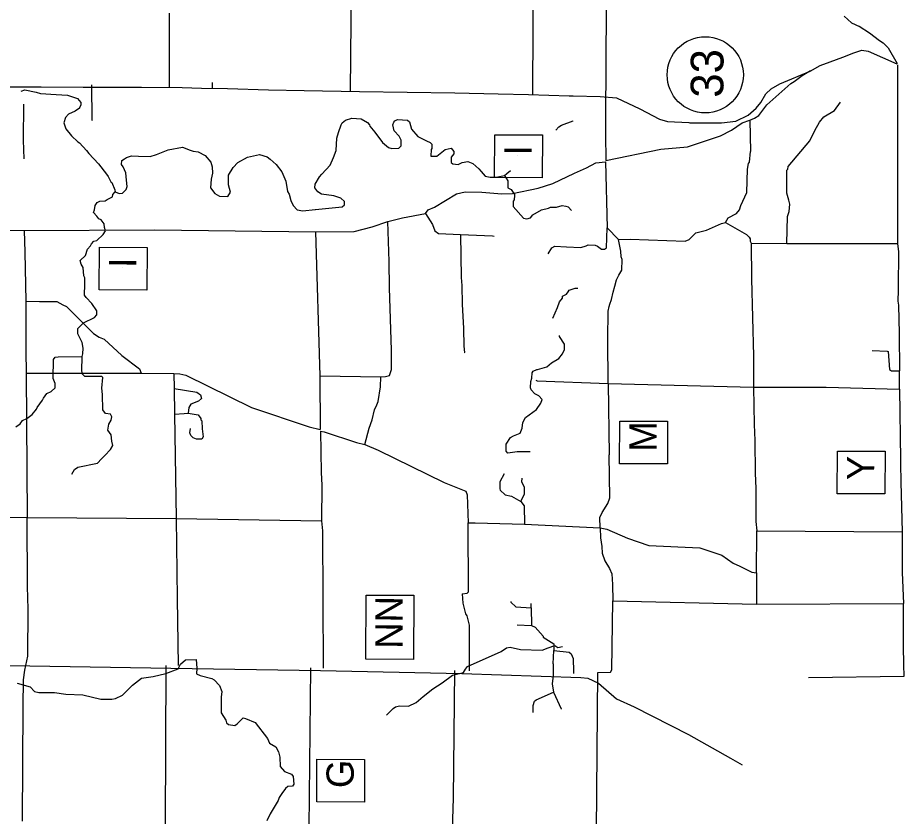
# Model space of a CAD drawing. Extents: x 299354 to 1325680, y 96128 to 228242.
# Drawn here: x 367783 to 400316, y 158651 to 187967 of the extents above; entities that cross this region are included whole.
import ezdxf

# ---------------------------------------------------------------- set-up
doc = ezdxf.new("R2010")
doc.units = 0
for name, color, linetype in [('Level 12', 7, 'Continuous'), ('Level 13', 7, 'Continuous'), ('Level 2', 7, 'Continuous'), ('Level 3', 7, 'Continuous'), ('Level 4', 7, 'Continuous'), ('Level 57', 7, 'Continuous')]:
    doc.layers.add(name, color=color, linetype=linetype)

msp = doc.modelspace()

# ---------------------------------------------------------------- linework, layer by layer
at = {"layer": 'Level 12'}
msp.add_line((393013, 185872), (393013, 185872), dxfattribs=at)
msp.add_circle((393013, 185872), 1398, dxfattribs=at)
at = {"layer": 'Level 13'}
for p, q in [((386137, 182916), (386137, 182916)), ((371631, 178789), (371631, 178789)), ((390728, 172406), (390728, 172406)), ((398712, 171305), (398712, 171305)), ((381418, 165641), (381418, 165641)), ((379612, 159993), (379612, 159993))]:
    msp.add_line(p, q, dxfattribs=at)
for points in [[(387031, 182095), (385281, 182102), (385287, 183672), (387037, 183665)], [(372525, 177967), (370775, 177974), (370782, 179544), (372532, 179537)], [(391622, 171585), (389872, 171592), (389879, 173162), (391629, 173155)], [(399606, 170484), (397856, 170491), (397862, 172061), (399612, 172054)], [(382311, 164410), (380561, 164417), (380570, 166772), (382320, 166765)], [(380506, 159171), (378756, 159178), (378762, 160748), (380512, 160741)]]:
    msp.add_lwpolyline(points, close=True, dxfattribs=at)
at = {"layer": 'Level 2'}
for points in [[(389386, 190375), (389347, 184284)], [(398113, 188030), (398378, 187777)], [(398378, 187777), (398678, 187650)], [(398656, 187660), (399042, 187413)], [(399042, 187413), (399406, 187135)], [(399406, 187135), (399547, 187050), (399729, 186865)], [(396860, 186008), (397233, 186212), (397597, 186345), (398063, 186521), (398461, 186680), (398765, 186780), (398992, 186743), (400048, 186276)], [(399729, 186865), (400055, 186283)], [(400065, 186237), (400065, 185837)], [(366798, 185430), (368641, 185430), (370184, 185424), (372319, 185421), (373812, 185408), (374529, 185385), (375479, 185368), (376980, 185321), (378289, 185292), (380324, 185257), (383818, 185209), (385410, 185178), (386528, 185151), (388020, 185104), (388170, 185103), (389154, 185077), (389762, 185022), (390609, 184623), (391331, 184249), (391622, 184155), (392414, 184115), (392448, 184114), (393615, 184104), (394141, 184174), (394585, 184387), (394879, 184651), (395048, 184857), (395235, 185172), (395428, 185362), (395747, 185543), (396860, 186008)], [(400065, 185837), (400067, 181020)], [(389347, 184284), (389358, 183675)], [(389358, 183675), (389366, 182725)], [(382844, 180918), (383078, 181016), (383883, 181500), (384201, 181580), (384818, 181558), (385543, 181502), (385935, 181515), (386879, 181715), (387423, 181876), (388211, 182261), (388654, 182457), (388998, 182637), (389349, 182676)], [(389349, 182676), (389410, 180250)], [(382743, 180785), (382844, 180918)], [(400067, 181020), (400071, 179678)], [(381364, 180489), (381907, 180618), (382743, 180785)], [(378716, 180105), (380126, 180117), (380787, 180295), (381364, 180489)], [(389410, 180250), (389831, 179821)], [(368013, 180152), (372813, 180184), (378716, 180105)], [(389449, 174541), (389439, 176166), (389448, 177200), (389491, 177366), (389509, 177457), (389577, 177623), (389630, 177890), (389698, 178114), (389751, 178347), (389836, 178521), (389954, 178703), (389958, 179095), (389925, 179195), (389910, 179395), (389831, 179821)], [(400071, 179678), (400102, 179370), (400089, 178053), (400089, 177970), (400085, 177562), (400100, 177411)], [(400100, 177411), (400124, 176378)], [(400124, 176378), (400145, 175003)], [(400138, 174328), (400145, 175003)], [(389449, 174541), (389491, 171916)], [(400138, 174328), (400173, 171736), (400173, 171702), (400172, 171669), (400172, 171636), (400172, 171602), (400190, 170919), (400240, 169093)], [(389158, 169244), (389145, 169619), (389230, 169801), (389441, 170133), (389510, 170340), (389491, 171916)], [(389158, 169244), (389171, 168868), (389218, 168560), (389233, 168310), (389330, 168034), (389503, 167749), (389584, 167548), (389614, 167156), (389625, 166564)], [(400240, 169093), (400243, 167602), (400283, 166468)], [(389075, 163928), (389534, 163940), (389585, 164023), (389625, 166564)], [(400316, 163792), (400304, 164209), (400285, 164909), (400287, 165093), (400283, 166468)], [(362794, 164216), (368222, 164173), (373407, 164090), (378898, 164004), (384084, 163889), (388448, 163742), (388700, 163718), (389098, 163543), (389755, 162963), (390404, 162669), (392403, 161659), (393940, 160782), (394369, 160544)], [(378481, 158223), (378535, 164106)], [(389022, 158094), (389075, 163928)]]:
    msp.add_lwpolyline(points, dxfattribs=at)
at = {"layer": 'Level 3'}
for points in [[(396273, 185621), (396567, 185844), (396877, 186024)], [(394650, 184203), (394826, 184284), (394977, 184383), (395273, 184772), (396156, 185556), (396273, 185621)], [(389366, 182725), (391388, 183140), (392356, 183223), (393577, 183637), (393971, 183834), (394366, 184114), (394650, 184203)], [(362813, 180188), (368013, 180152)], [(368017, 180152), (368043, 179360)], [(368043, 179360), (368076, 177560)], [(368076, 177560), (368084, 175735)], [(368084, 175735), (368094, 174918)], [(368094, 174918), (368128, 169617)], [(367959, 158477), (367981, 162693), (367990, 163660), (368043, 164010), (368148, 164534), (368164, 166250), (368138, 167092), (368128, 169617)]]:
    msp.add_lwpolyline(points, dxfattribs=at)
at = {"layer": 'Level 4'}
for points in [[(386702, 193200), (386714, 192675), (386678, 185150)], [(380022, 187843), (380036, 189310)], [(373345, 188137), (373338, 186051)], [(379999, 185277), (380022, 187843)], [(373338, 186051), (373336, 185412)], [(370493, 185508), (370493, 185505), (370498, 184213), (370514, 184196)], [(374917, 185585), (374915, 185383)], [(367993, 184793), (367981, 183477), (368002, 182787)], [(396061, 182506), (396853, 183449), (397040, 183823), (397210, 184129), (397370, 184328), (397756, 184558), (397975, 184862)], [(394650, 184203), (394673, 183061)], [(393756, 180444), (393858, 180618), (394160, 180782), (394270, 180914), (394321, 181072), (394542, 181545), (394567, 182403), (394602, 182611), (394636, 182661), (394673, 183061)], [(396001, 179682), (396027, 180665), (396095, 180848), (396115, 181123), (396083, 181273), (396002, 181524), (396009, 182374), (396043, 182407), (396061, 182506)], [(382743, 180785), (383006, 180375), (383087, 180140), (383220, 180048), (384036, 180007)], [(381111, 174783), (381278, 174798), (381428, 174830), (381497, 175055), (381504, 175763), (381425, 178055), (381417, 179014), (381364, 180489)], [(387249, 179303), (387385, 179518), (387494, 179576), (387927, 179555), (388452, 179534), (388645, 179599), (388712, 179631), (388970, 179612), (389053, 179578), (389202, 179468), (389319, 179467), (389386, 179525), (389410, 180250)], [(389831, 179821), (390256, 179834), (392274, 179766), (392425, 179831), (392669, 180070), (393053, 180167), (393614, 180412), (393756, 180444)], [(393756, 180444), (394528, 180004), (394627, 179911), (394660, 179844), (394659, 179761), (394692, 179694)], [(378716, 180105), (378868, 174820)], [(384036, 180007), (384055, 178432), (384086, 178131), (384096, 177448), (384138, 176556)], [(384036, 180007), (385204, 179963), (385261, 179946)], [(394692, 179694), (394705, 178385)], [(394692, 179694), (396001, 179682)], [(396001, 179682), (400071, 179678)], [(394705, 178385), (394779, 175543), (394785, 174409)], [(368076, 177560), (368585, 177555)], [(368585, 177555), (369219, 177549), (369435, 177431)], [(369435, 177431), (369567, 177363), (370171, 176766), (370559, 176370), (370766, 176235), (370949, 176167), (371602, 175569), (372248, 175072), (372314, 174913)], [(384138, 176556), (384149, 175906), (384180, 175672), (384189, 175659)], [(399134, 175753), (399693, 175732), (399726, 175715), (399770, 175056), (399853, 175005), (400145, 175003)], [(368094, 174918), (372314, 174913)], [(372314, 174913), (373514, 174902)], [(373514, 174902), (373526, 174360)], [(373514, 174902), (373731, 174900), (373956, 174848), (376364, 173660), (378475, 172949), (378883, 172845)], [(378868, 174820), (378883, 172845)], [(378868, 174820), (381111, 174783)], [(380521, 172297), (380685, 172895), (380788, 173211), (380875, 173569), (380960, 173751), (381011, 173876), (381099, 174417), (381111, 174783)], [(386799, 174667), (386839, 174631), (389449, 174541)], [(389449, 174541), (394785, 174409)], [(394785, 174409), (394806, 173034), (394834, 172442), (394839, 171242), (394867, 170684), (394873, 169475), (394903, 169125)], [(394785, 174409), (397445, 174402)], [(397445, 174402), (400138, 174328)], [(373526, 174360), (373534, 173418)], [(373526, 174360), (374359, 174219), (374491, 174118), (374523, 173985), (374422, 173894), (374130, 173780), (374062, 173664), (374043, 173447)], [(373534, 173418), (373893, 173432), (374043, 173447)], [(373534, 173418), (373599, 169584)], [(374043, 173447), (374401, 173386), (374500, 173251), (374500, 173201), (374533, 173168), (374547, 172876), (374594, 172576), (374543, 172493), (374343, 172494), (374218, 172546), (374136, 172630), (374103, 172730), (374121, 172888)], [(378899, 172787), (378919, 171270), (378948, 170811), (378936, 169503)], [(378899, 172787), (379024, 172769), (380221, 172375), (380521, 172297)], [(380521, 172297), (381011, 172092), (383427, 170904), (384225, 170588), (384274, 170454), (384314, 169421)], [(385632, 171226), (385479, 170935), (385477, 170677), (385493, 170627), (385675, 170458), (385899, 170406), (386248, 170203)], [(386248, 170203), (386375, 170485), (386378, 170727), (386288, 170928), (386289, 171061)], [(386248, 170203), (386371, 170044), (386382, 169369)], [(362886, 169648), (368128, 169617)], [(368128, 169617), (373599, 169584)], [(373599, 169584), (378936, 169503)], [(373599, 169584), (373635, 166646)], [(378936, 169503), (378965, 169128), (378994, 164085)], [(384098, 166814), (384274, 166846), (384324, 166896), (384314, 169421)], [(384314, 169421), (384564, 169418), (386382, 169369)], [(386382, 169369), (389158, 169244)], [(389158, 169244), (389399, 169191), (390155, 168860), (390945, 168586), (392812, 168510), (393627, 168236), (394041, 167941), (394282, 167839), (394722, 167618), (394889, 167583)], [(394889, 167583), (394903, 169125)], [(394903, 169125), (400240, 169093)], [(394889, 167583), (394895, 166442)], [(373635, 166646), (373666, 164184)], [(384098, 166814), (384112, 166473), (384217, 166088), (384266, 166013), (384346, 165662), (384349, 164170), (384347, 163987)], [(385880, 166532), (385880, 166507), (386062, 166338), (386620, 166300)], [(386620, 166300), (386622, 166466)], [(386620, 166300), (386631, 165658)], [(389625, 166564), (394895, 166442)], [(394895, 166442), (400283, 166468)], [(386106, 165679), (386631, 165658)], [(386631, 165658), (386772, 165590), (387070, 165262), (387069, 165229), (387459, 164976), (387457, 164734)], [(387435, 164242), (387457, 164734)], [(387457, 164734), (388015, 164679), (388098, 164611), (388163, 164444), (388175, 163969), (388174, 163894)], [(373215, 164188), (373195, 158329)], [(383735, 158159), (383779, 159317), (383822, 164008)], [(387435, 164242), (387431, 163817), (387395, 163518), (387443, 163209)], [(396805, 163749), (400316, 163792)], [(386702, 162457), (386704, 162724), (386747, 162882), (386814, 162931), (387443, 163209)], [(387443, 163209), (387720, 162598), (387737, 162581)]]:
    msp.add_lwpolyline(points, dxfattribs=at)
at = {"layer": 'Level 57'}
for points in [[(367915, 185270), (368042, 185316)], [(368042, 185316), (368049, 185318), (368457, 185231), (368623, 185180), (369198, 185145)], [(369199, 185145), (369606, 185121), (369981, 185001), (370096, 184858), (370095, 184758), (370044, 184675), (370044, 184642), (369893, 184543), (369650, 184429), (369532, 184305), (369480, 184105), (369545, 183888), (369751, 183628), (369983, 183409), (370049, 183375), (370305, 183098), (370387, 182981), (370748, 182605)], [(378707, 180925), (379693, 181030), (379777, 181096), (379778, 181221), (379646, 181338), (379388, 181424), (378930, 181495), (378798, 181579), (378682, 181722), (378700, 181855), (378853, 182121), (378937, 182228), (379249, 182559), (379368, 182833), (379471, 183098), (379491, 183540), (379560, 183756), (379654, 184030), (379688, 184113), (379806, 184212), (380040, 184277), (380382, 184257), (380614, 184121), (380689, 184037), (380705, 183987), (380886, 183769), (381166, 183391), (381390, 183198), (381506, 183163), (381765, 183178), (381849, 183268), (381851, 183468), (381786, 183619), (381596, 183812), (381547, 184030), (381582, 184129), (381616, 184179), (381724, 184228), (382091, 184208), (382157, 184141), (382238, 183873), (382461, 183613), (382785, 183443), (382918, 183392), (382984, 183325), (382982, 183167), (382949, 183134), (382946, 182884)], [(387526, 183838), (387635, 183958), (387736, 184024), (388162, 184186), (388165, 184187)], [(371699, 182789), (371770, 182835), (371963, 182900), (372213, 182881), (372638, 182877), (372881, 182941), (373299, 183121), (373826, 183216), (374112, 183104)], [(382946, 182884), (383163, 182882), (383474, 183129), (383691, 183177), (383790, 183059), (383790, 182976), (383688, 182843), (383686, 182652), (383753, 182601), (383944, 182583), (384095, 182648), (384296, 182688), (384487, 182611), (384702, 182426), (384784, 182325), (384941, 182149), (385124, 182114), (385341, 182112), (385650, 182176)], [(374113, 183103), (374216, 183063), (374399, 183044)], [(374399, 183044), (374657, 182909), (374871, 182665), (374920, 182498), (374926, 182264), (374882, 182040), (374863, 181723), (375019, 181514), (375185, 181412), (375494, 181409), (375595, 181558), (375514, 181834), (375517, 182184), (375687, 182474), (375855, 182656), (376216, 182844), (376659, 182940), (376941, 182855), (377049, 182770), (377264, 182577), (377478, 182308), (377617, 181965), (377680, 181590)], [(370748, 182605), (370751, 182602), (371039, 182225), (371105, 182141), (371203, 181940), (371237, 181923), (371342, 181647), (371359, 181580)], [(371359, 181580), (371508, 181512), (371625, 181528), (371760, 181660), (371794, 181768), (371779, 182001), (371749, 182277), (371651, 182494), (371585, 182578), (371603, 182728), (371699, 182789)], [(385650, 182176), (385734, 182250), (385865, 182363)], [(385650, 182176), (385765, 181975), (385763, 181725), (385887, 181657), (386019, 181481), (386019, 181447)], [(370143, 175533), (370169, 175632), (370188, 175832), (370148, 176041), (369984, 176359), (369986, 176559), (370197, 176765), (370599, 176962), (370683, 177061), (370684, 177203), (370503, 177471), (370289, 177698), (370239, 177782), (370243, 178190), (370245, 178423), (370212, 178490), (370190, 178799), (370108, 178916), (370076, 179050), (370269, 179240), (370338, 179473), (370456, 179588), (370490, 179671), (370574, 179762), (370692, 179794), (370919, 180009), (371003, 180142), (370971, 180267), (370956, 180400), (370840, 180551), (370757, 180585), (370683, 180686), (370567, 180812), (370602, 180912), (370620, 181078), (370704, 181178), (370796, 181227), (370997, 181242), (371064, 181299), (371265, 181398), (371274, 181481), (371359, 181580)], [(377680, 181590), (377746, 181489), (377811, 181255), (377892, 181079), (378041, 180911), (378249, 180876), (378703, 180924)], [(386019, 181447), (386001, 181281), (385967, 181231), (385965, 181040), (386345, 180603), (386470, 180585), (386603, 180617), (386688, 180733), (386998, 180913), (387265, 180978), (387333, 181010), (387558, 181008), (387758, 181073), (387892, 181055), (387983, 181021), (388099, 180892)], [(386019, 181447), (386036, 181447)], [(387420, 176935), (387590, 177333), (387659, 177541), (387777, 177673), (387778, 177740), (387920, 177822), (387988, 177904), (388022, 177962), (388239, 178044), (388339, 178043)], [(386591, 172025), (386115, 172030), (385773, 171983), (385707, 172050), (385709, 172308), (385870, 172557), (385971, 172623), (386222, 172720), (386290, 172895), (386317, 173103), (386419, 173285), (386822, 173582), (386983, 173822), (387034, 173955), (386902, 174089), (386761, 174157), (386628, 174308), (386596, 174384), (386615, 174617), (386649, 174733), (386659, 174925), (386702, 174991), (386836, 175056), (386861, 175056), (387195, 175153), (387372, 175302), (387640, 175458), (387775, 175623), (387843, 175789), (387845, 175981), (387664, 176266), (387664, 176299)], [(367718, 172946), (367869, 173061), (367953, 173177), (368113, 173259), (368314, 173407), (368466, 173598), (368500, 173664), (368694, 173929), (368728, 174004), (368847, 174169), (369014, 174251), (369157, 174383), (369159, 174541), (369085, 174725), (369092, 175417), (369151, 175500), (369268, 175524), (370143, 175533)], [(369770, 171211), (369872, 171385), (369989, 171467), (370708, 171611), (370859, 171776), (370977, 171900), (371188, 172115), (371273, 172264), (371241, 172423), (371209, 172656), (371086, 172824), (371121, 173049), (371214, 173198), (371232, 173314), (371191, 173415), (371008, 173441), (370909, 173576), (370898, 174134), (370867, 174368), (370904, 174759), (370871, 174793), (370245, 174798), (370154, 174882), (370130, 174999), (370143, 175533)], [(381314, 162364), (381558, 162604), (381642, 162670), (381793, 162702), (382118, 162699), (382403, 162830), (382663, 163052), (383016, 163332), (383360, 163554), (383738, 163834), (384147, 163930), (384215, 164055), (384283, 164154), (385522, 164701), (385715, 164833), (385849, 164865)], [(385849, 164865), (386232, 164778), (387032, 164754), (387250, 164836), (387493, 164917), (387609, 164849), (387777, 164888)], [(367764, 163537), (368238, 163399), (368404, 163231), (368562, 163197), (369137, 163191), (369545, 163138), (370171, 163115), (370828, 162951), (371237, 162947), (371370, 162979), (371622, 163102), (372000, 163465), (372328, 163721), (372754, 163784), (373214, 163896), (373665, 164067), (373759, 164233), (373944, 164398), (374336, 164411)], [(374336, 164411), (374350, 164094), (374348, 163886), (374480, 163818), (374905, 163714), (374988, 163663), (375186, 163453), (375267, 163236), (375249, 163019), (375244, 162453), (375416, 162184), (375449, 162084), (375515, 162017), (375748, 161981), (375840, 162047), (376059, 162262), (376142, 162245), (376499, 162091), (376953, 161512), (377018, 161337), (377250, 161201), (377357, 161017), (377405, 160825), (377419, 160475), (377567, 160298), (377833, 160196), (377891, 160112), (377921, 159828), (377871, 159754), (377695, 159739), (377611, 159673), (377476, 159491), (377375, 159342), (377340, 159234), (377044, 158745), (376925, 158479)]]:
    msp.add_lwpolyline(points, dxfattribs=at)

# ---------------------------------------------------------------- texts
at = {"layer": 'Level 12'}
msp.add_text('33', height=1200, rotation=89.767, dxfattribs=at).set_placement((393677, 185029))
at = {"layer": 'Level 13'}
for s, p in [('I', (386637, 182910)), ('I', (372131, 178783)), ('M', (391227, 172034)), ('Y', (399210, 170988)), ('NN', (381903, 164798)), ('G', (380111, 159684))]:
    msp.add_text(s, height=1000, rotation=89.767, dxfattribs=at).set_placement(p)

doc.saveas('drawing.dxf')
